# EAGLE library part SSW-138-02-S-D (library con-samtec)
THROUGH-HOLE .025" SQ POST SOCKET Source: Samtec SSW.pdf
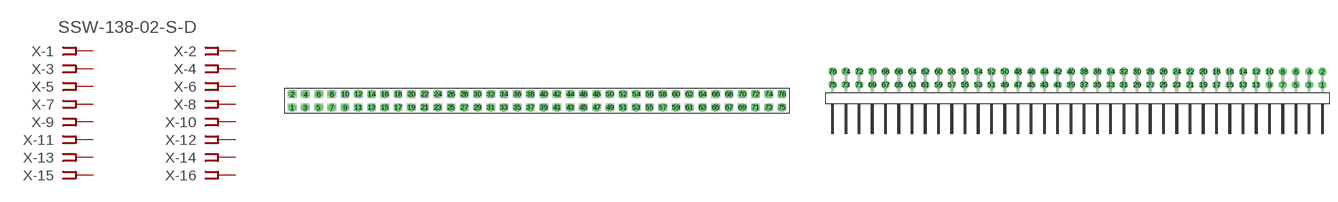
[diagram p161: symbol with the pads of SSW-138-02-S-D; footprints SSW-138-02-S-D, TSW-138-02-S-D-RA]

Designator prefix X; gates -1=FPINV -2=FPIN -3=FPIN -4=FPIN -5=FPIN -6=FPIN -7=FPIN -8=FPIN -9=FPIN -10=FPIN -11=FPIN -12=FPIN -13=FPIN -14=FPIN -15=FPIN -16=FPIN -17=FPIN -18=FPIN -19=FPIN -20=FPIN -21=FPIN -22=FPIN -23=FPIN -24=FPIN -25=FPIN -26=FPIN -27=FPIN -28=FPIN -29=FPIN -30=FPIN -31=FPIN -32=FPIN -33=FPIN -34=FPIN -35=FPIN -36=FPIN -37=FPIN -38=FPIN -39=FPIN -40=FPIN -41=FPIN -42=FPIN -43=FPIN -44=FPIN -45=FPIN -46=FPIN -47=FPIN -48=FPIN -49=FPIN -50=FPIN -51=FPIN -52=FPIN -53=FPIN -54=FPIN -55=FPIN -56=FPIN -57=FPIN -58=FPIN -59=FPIN -60=FPIN -61=FPIN -62=FPIN -63=FPIN -64=FPIN -65=FPIN -66=FPIN -67=FPIN -68=FPIN -69=FPIN -70=FPIN -71=FPIN -72=FPIN -73=FPIN -74=FPIN -75=FPIN -76=FPIN

## SSW-138-02-S-D (MPN: SSW-138-02-S-D; OC_FARNELL: unknown; OC_NEWARK: 11P9928)  [SSW-138-02-S-D]
1  -1:1  pas
2  -2:1  pas
3  -3:1  pas
4  -4:1  pas
5  -5:1  pas
6  -6:1  pas
7  -7:1  pas
8  -8:1  pas
9  -9:1  pas
10  -10:1  pas
11  -11:1  pas
12  -12:1  pas
13  -13:1  pas
14  -14:1  pas
15  -15:1  pas
16  -16:1  pas
17  -17:1  pas
18  -18:1  pas
19  -19:1  pas
20  -20:1  pas
21  -21:1  pas
22  -22:1  pas
23  -23:1  pas
24  -24:1  pas
25  -25:1  pas
26  -26:1  pas
27  -27:1  pas
28  -28:1  pas
29  -29:1  pas
30  -30:1  pas
31  -31:1  pas
32  -32:1  pas
33  -33:1  pas
34  -34:1  pas
35  -35:1  pas
36  -36:1  pas
37  -37:1  pas
38  -38:1  pas
39  -39:1  pas
40  -40:1  pas
41  -41:1  pas
42  -42:1  pas
43  -43:1  pas
44  -44:1  pas
45  -45:1  pas
46  -46:1  pas
47  -47:1  pas
48  -48:1  pas
49  -49:1  pas
50  -50:1  pas
51  -51:1  pas
52  -52:1  pas
53  -53:1  pas
54  -54:1  pas
55  -55:1  pas
56  -56:1  pas
57  -57:1  pas
58  -58:1  pas
59  -59:1  pas
60  -60:1  pas
61  -61:1  pas
62  -62:1  pas
63  -63:1  pas
64  -64:1  pas
65  -65:1  pas
66  -66:1  pas
67  -67:1  pas
68  -68:1  pas
69  -69:1  pas
70  -70:1  pas
71  -71:1  pas
72  -72:1  pas
73  -73:1  pas
74  -74:1  pas
75  -75:1  pas
76  -76:1  pas

## SSW-138-02-S-D-RA (MPN: SSW-138-02-S-D-RA; OC_FARNELL: unknown; OC_NEWARK: 11P9929)  [TSW-138-02-S-D-RA]
Pads as for SSW-138-02-S-D

## Footprint SSW-138-02-S-D (pad centres in mm)
THROUGH-HOLE .025" SQ POST SOCKET Source: Samtec SSW.pdf
drill 1 pad 1.5 octagon: 1 -46.99,-1.27; 2 -46.99,1.27; 3 -44.45,-1.27; 4 -44.45,1.27; 5 -41.91,-1.27; 6 -41.91,1.27; 7 -39.37,-1.27; 8 -39.37,1.27; 9 -36.83,-1.27; 10 -36.83,1.27; 11 -34.29,-1.27; 12 -34.29,1.27; 13 -31.75,-1.27; 14 -31.75,1.27; 15 -29.21,-1.27; 16 -29.21,1.27; 17 -26.67,-1.27; 18 -26.67,1.27; 19 -24.13,-1.27; 20 -24.13,1.27; 21 -21.59,-1.27; 22 -21.59,1.27; 23 -19.05,-1.27; 24 -19.05,1.27; 25 -16.51,-1.27; 26 -16.51,1.27; 27 -13.97,-1.27; 28 -13.97,1.27; 29 -11.43,-1.27; 30 -11.43,1.27; 31 -8.89,-1.27; 32 -8.89,1.27; 33 -6.35,-1.27; 34 -6.35,1.27; 35 -3.81,-1.27; 36 -3.81,1.27; 37 -1.27,-1.27; 38 -1.27,1.27; 39 1.27,-1.27; 40 1.27,1.27; 41 3.81,-1.27; 42 3.81,1.27; 43 6.35,-1.27; 44 6.35,1.27; 45 8.89,-1.27; 46 8.89,1.27; 47 11.43,-1.27; 48 11.43,1.27; 49 13.97,-1.27; 50 13.97,1.27; 51 16.51,-1.27; 52 16.51,1.27; 53 19.05,-1.27; 54 19.05,1.27; 55 21.59,-1.27; 56 21.59,1.27; 57 24.13,-1.27; 58 24.13,1.27; 59 26.67,-1.27; 60 26.67,1.27; 61 29.21,-1.27; 62 29.21,1.27; 63 31.75,-1.27; 64 31.75,1.27; 65 34.29,-1.27; 66 34.29,1.27; 67 36.83,-1.27; 68 36.83,1.27; 69 39.37,-1.27; 70 39.37,1.27; 71 41.91,-1.27; 72 41.91,1.27; 73 44.45,-1.27; 74 44.45,1.27; 75 46.99,-1.27; 76 46.99,1.27

## Footprint TSW-138-02-S-D-RA (pad centres in mm)
THROUGH-HOLE .025" SQ POST HEADER Source: Samtec TSW.pdf
drill 1 pad 1.5 octagon: 1 46.99,1.524; 2 46.99,4.064; 3 44.45,1.524; 4 44.45,4.064; 5 41.91,1.524; 6 41.91,4.064; 7 39.37,1.524; 8 39.37,4.064; 9 36.83,1.524; 10 36.83,4.064; 11 34.29,1.524; 12 34.29,4.064; 13 31.75,1.524; 14 31.75,4.064; 15 29.21,1.524; 16 29.21,4.064; 17 26.67,1.524; 18 26.67,4.064; 19 24.13,1.524; 20 24.13,4.064; 21 21.59,1.524; 22 21.59,4.064; 23 19.05,1.524; 24 19.05,4.064; 25 16.51,1.524; 26 16.51,4.064; 27 13.97,1.524; 28 13.97,4.064; 29 11.43,1.524; 30 11.43,4.064; 31 8.89,1.524; 32 8.89,4.064; 33 6.35,1.524; 34 6.35,4.064; 35 3.81,1.524; 36 3.81,4.064; 37 1.27,1.524; 38 1.27,4.064; 39 -1.27,1.524; 40 -1.27,4.064; 41 -3.81,1.524; 42 -3.81,4.064; 43 -6.35,1.524; 44 -6.35,4.064; 45 -8.89,1.524; 46 -8.89,4.064; 47 -11.43,1.524; 48 -11.43,4.064; 49 -13.97,1.524; 50 -13.97,4.064; 51 -16.51,1.524; 52 -16.51,4.064; 53 -19.05,1.524; 54 -19.05,4.064; 55 -21.59,1.524; 56 -21.59,4.064; 57 -24.13,1.524; 58 -24.13,4.064; 59 -26.67,1.524; 60 -26.67,4.064; 61 -29.21,1.524; 62 -29.21,4.064; 63 -31.75,1.524; 64 -31.75,4.064; 65 -34.29,1.524; 66 -34.29,4.064; 67 -36.83,1.524; 68 -36.83,4.064; 69 -39.37,1.524; 70 -39.37,4.064; 71 -41.91,1.524; 72 -41.91,4.064; 73 -44.45,1.524; 74 -44.45,4.064; 75 -46.99,1.524; 76 -46.99,4.064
